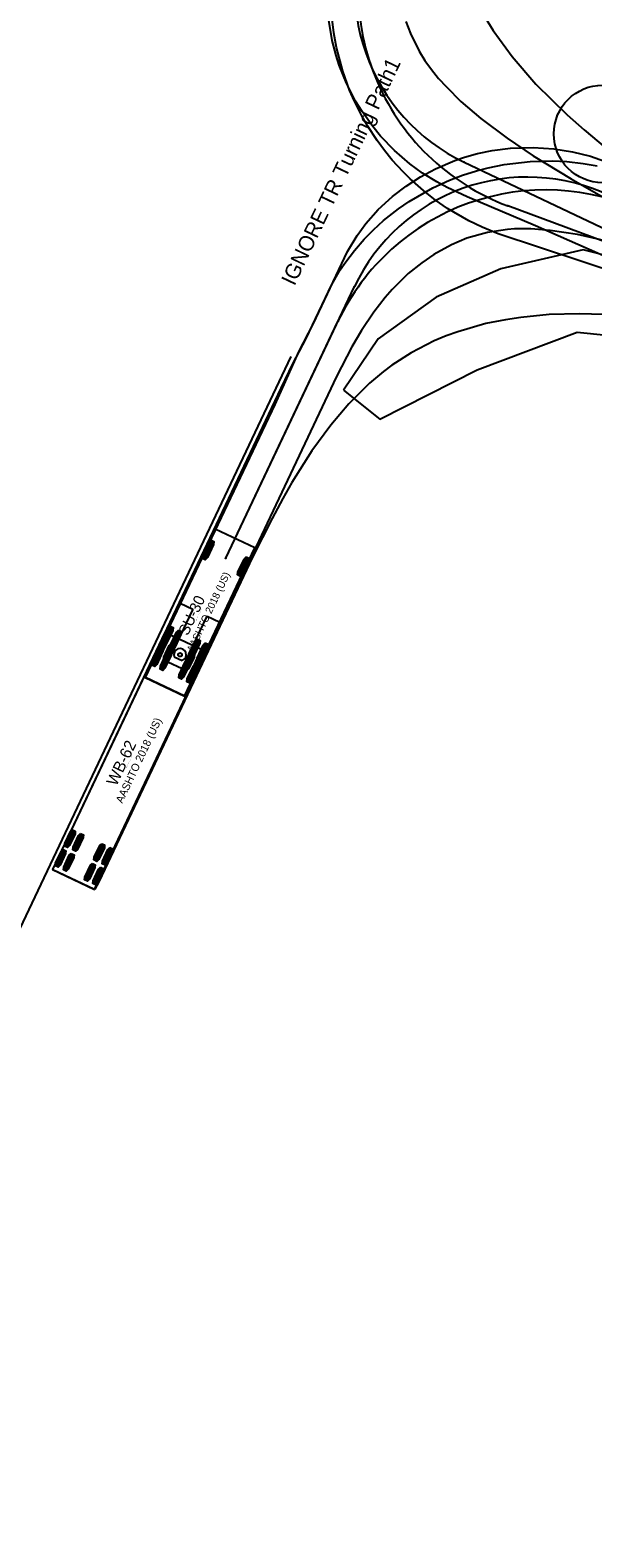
# Model space of a CAD drawing. Extents: x 186128 to 186702, y 352195 to 353183.
# Drawn here: x 186398.8 to 186501.6, y 352684.3 to 352960 of the extents above; entities that cross this region are included whole.
import ezdxf

# ---------------------------------------------------------------- set-up
doc = ezdxf.new("R2010")
doc.units = 0
for name, color, linetype in [('GK_Drainage_Nodes', 7, 'Continuous'), ('SV_X_Control_Cells_Found', 7, 'Continuous'), ('SV_X_Shot_Marker', 7, 'Continuous')]:
    doc.layers.add(name, color=color, linetype=linetype)

msp = doc.modelspace()

# ---------------------------------------------------------------- linework, layer by layer
at = {"layer": 'GK_Drainage_Nodes'}
msp.add_lwpolyline([(186455.99, 352894.17), (186462.66, 352888.85), (186480.45, 352897.88), (186498.71, 352904.75), (186519.8, 352902.65), (186541.45, 352895.17), (186544.58, 352902.76), (186518.65, 352915.08), (186499.81, 352919.82), (186484.74, 352916.37), (186472.96, 352911.19), (186462.32, 352903.52)], close=True, dxfattribs=at)
msp.add_circle((186503.37, 352941), 8.93, dxfattribs=at)
at = {"layer": 'SV_X_Control_Cells_Found'}
for p, q in [((186478.03, 352935.86), (186665.94, 352846.44)), ((186434.48, 352863.41), (186458, 352913.08)), ((186344.15, 352684.3), (186446.42, 352900.31)), ((186432.58, 352868.73), (186419.74, 352841.62)), ((186431.77, 352866.54), (186430.34, 352863.52)), ((186439.81, 352865.31), (186432.58, 352868.73)), ((186432.58, 352868.73), (186432.58, 352868.73)), ((186426.97, 352838.2), (186439.81, 352865.31)), ((186431.96, 352866.45), (186430.53, 352863.43)), ((186432.15, 352866.36), (186430.72, 352863.34)), ((186438.25, 352863.47), (186436.82, 352860.46)), ((186438.44, 352863.38), (186437.01, 352860.37)), ((186438.62, 352863.29), (186437.2, 352860.28)), ((186423.21, 352848.46), (186421.78, 352845.45)), ((186423.4, 352848.37), (186421.97, 352845.36)), ((186423.59, 352848.28), (186422.16, 352845.27)), ((186424.57, 352847.82), (186423.14, 352844.8)), ((186424.76, 352847.73), (186423.33, 352844.72)), ((186424.94, 352847.64), (186423.52, 352844.63)), ((186428.33, 352846.03), (186426.91, 352843.02)), ((186428.52, 352845.95), (186427.09, 352842.93)), ((186428.71, 352845.86), (186427.28, 352842.84)), ((186429.69, 352845.39), (186428.26, 352842.38)), ((186429.88, 352845.3), (186428.45, 352842.29)), ((186430.07, 352845.21), (186428.64, 352842.2)), ((186419.74, 352841.62), (186426.97, 352838.2))]:
    msp.add_line(p, q, dxfattribs=at)
for points in [[(186505.05, 352918.05), (186491.07, 352924.21), (186478.6, 352929.53), (186474.96, 352931.2), (186473.06, 352932.22), (186470.44, 352933.86), (186468.11, 352935.57), (186465.35, 352937.96), (186462.79, 352940.62), (186461.35, 352942.36), (186459.41, 352945.08), (186458.23, 352947.02), (186456.56, 352950.26), (186455.21, 352953.61), (186454.65, 352955.32), (186453.93, 352958.07), (186453.31, 352961.78)], [(186467.42, 352961.58), (186468.24, 352959.38), (186469.81, 352956.17), (186470.89, 352954.43), (186472.08, 352952.79), (186473.39, 352951.15), (186474.8, 352949.61), (186477.46, 352946.95), (186481.13, 352943.8), (186485.89, 352940.22), (186490.68, 352937.01), (186497.6, 352932.78), (186503.05, 352929.69), (186509.05, 352926.44), (186518.63, 352921.46), (186534.9, 352913.39), (186572.4, 352895.37), (186616.63, 352874.31)], [(186504.13, 352921.4), (186498.78, 352922.61), (186493.76, 352923.37), (186490.21, 352923.63), (186487.23, 352923.63), (186485.95, 352923.53), (186482.34, 352923.01), (186478.57, 352921.92), (186475.75, 352920.74), (186472.53, 352918.97), (186470.3, 352917.46), (186467.84, 352915.46), (186464.89, 352912.57), (186463.61, 352911.1), (186461.54, 352908.44), (186459.28, 352905.06), (186457.54, 352902.07), (186454.75, 352896.66), (186427.85, 352839.8), (186427.09, 352838.26), (186426.99, 352838.23), (186419.81, 352841.64), (186443.5, 352891.51), (186447.86, 352901.16), (186450.45, 352906.21), (186456.75, 352919.53), (186458.49, 352922.45), (186460.1, 352924.61), (186462.36, 352927.17), (186464.95, 352929.57), (186467.45, 352931.47), (186470.07, 352933.18), (186472.79, 352934.62), (186476.34, 352936.13), (186478.14, 352936.75), (186480.5, 352937.41), (186483.19, 352937.97), (186486.54, 352938.39), (186490.67, 352938.52), (186494.45, 352938.26), (186497.83, 352937.74), (186501.14, 352936.92), (186504.58, 352935.74)], [(186431.72, 352866.56), (186432.19, 352866.34), (186432.13, 352865.85), (186431.11, 352863.68), (186430.77, 352863.32), (186430.3, 352863.55), (186430.35, 352864.03), (186431.38, 352866.2), (186431.72, 352866.56)], [(186438.2, 352863.49), (186438.67, 352863.27), (186438.61, 352862.78), (186437.59, 352860.61), (186437.24, 352860.26), (186436.77, 352860.48), (186436.83, 352860.97), (186437.86, 352863.14), (186438.2, 352863.49)], [(186423.16, 352848.48), (186423.63, 352848.26), (186423.58, 352847.77), (186422.55, 352845.6), (186422.21, 352845.25), (186421.74, 352845.47), (186421.8, 352845.96), (186422.82, 352848.13), (186423.16, 352848.48)], [(186424.52, 352847.84), (186424.99, 352847.62), (186424.93, 352847.13), (186423.91, 352844.96), (186423.56, 352844.6), (186423.09, 352844.83), (186423.15, 352845.32), (186424.18, 352847.48), (186424.52, 352847.84)], [(186428.29, 352846.06), (186428.76, 352845.83), (186428.7, 352845.35), (186427.67, 352843.18), (186427.33, 352842.82), (186426.86, 352843.04), (186426.92, 352843.53), (186427.94, 352845.7), (186428.29, 352846.06)], [(186429.64, 352845.41), (186430.11, 352845.19), (186430.05, 352844.7), (186429.03, 352842.53), (186428.69, 352842.18), (186428.22, 352842.4), (186428.27, 352842.89), (186429.3, 352845.06), (186429.64, 352845.41)]]:
    msp.add_lwpolyline(points, dxfattribs=at)
for centre in [(186478.03, 352935.86), (186478.03, 352935.86), (186458, 352913.08), (186458, 352913.08), (186434.48, 352863.41)]:
    msp.add_circle(centre, 0.0417, dxfattribs=at)
for centre, start, end in [((186493.07, 352967.47), 154.3603, 244.5505), ((186489.64, 352898.11), 64.5505, 154.6637)]:
    msp.add_arc(centre, 35, start, end, dxfattribs=at)
at = {"layer": 'SV_X_Shot_Marker'}
for p, q in [((186526.61, 352912.75), (186486.06, 352927.85)), ((186434.48, 352863.41), (186455, 352906.74)), ((186432.58, 352868.73), (186426.16, 352855.18)), ((186431.86, 352866.68), (186430.29, 352863.36)), ((186432.07, 352866.58), (186430.5, 352863.27)), ((186439.81, 352865.31), (186432.58, 352868.73)), ((186432.58, 352868.73), (186432.58, 352868.73)), ((186432.27, 352866.48), (186430.71, 352863.17)), ((186433.39, 352851.75), (186439.81, 352865.31)), ((186438.26, 352863.65), (186436.69, 352860.33)), ((186438.47, 352863.55), (186436.9, 352860.23)), ((186438.68, 352863.45), (186437.11, 352860.14)), ((186428.48, 352854.08), (186423.94, 352844.5)), ((186426.16, 352855.18), (186428.48, 352854.08)), ((186426.54, 352843.27), (186431.07, 352852.85)), ((186431.07, 352852.85), (186433.39, 352851.75)), ((186424.41, 352850.95), (186422.84, 352847.64)), ((186424.62, 352850.85), (186423.05, 352847.54)), ((186424.83, 352850.75), (186423.26, 352847.44)), ((186425.91, 352850.24), (186424.34, 352846.93)), ((186426.11, 352850.15), (186424.54, 352846.83)), ((186426.32, 352850.05), (186424.75, 352846.73)), ((186423.37, 352849.86), (186402.83, 352806.48)), ((186431.05, 352846.22), (186423.37, 352849.86)), ((186423.37, 352849.86), (186423.37, 352849.86)), ((186429.32, 352848.63), (186427.76, 352845.31)), ((186429.53, 352848.53), (186427.96, 352845.21)), ((186429.74, 352848.43), (186428.17, 352845.12)), ((186430.82, 352847.92), (186429.25, 352844.61)), ((186431.02, 352847.82), (186429.45, 352844.51)), ((186431.23, 352847.72), (186429.66, 352844.41)), ((186410.51, 352802.84), (186431.05, 352846.22)), ((186422.62, 352847.15), (186421.05, 352843.84)), ((186422.82, 352847.06), (186421.25, 352843.74)), ((186423.03, 352846.96), (186421.46, 352843.64)), ((186424.11, 352846.45), (186422.54, 352843.13)), ((186424.32, 352846.35), (186422.75, 352843.04)), ((186424.52, 352846.25), (186422.95, 352842.94)), ((186423.94, 352844.5), (186426.54, 352843.27)), ((186425.06, 352845.4), (186426.52, 352844.71)), ((186427.53, 352844.83), (186425.96, 352841.52)), ((186427.73, 352844.73), (186426.17, 352841.42)), ((186427.94, 352844.63), (186426.37, 352841.32)), ((186429.02, 352844.12), (186427.45, 352840.81)), ((186429.23, 352844.03), (186427.66, 352840.71)), ((186429.43, 352843.93), (186427.86, 352840.61)), ((186406.52, 352813.75), (186405.11, 352810.76)), ((186406.73, 352813.65), (186405.32, 352810.66)), ((186406.94, 352813.55), (186405.52, 352810.57)), ((186408.01, 352813.04), (186406.6, 352810.06)), ((186408.22, 352812.94), (186406.81, 352809.96)), ((186408.43, 352812.84), (186407.01, 352809.86)), ((186404.81, 352810.13), (186403.4, 352807.15)), ((186405.02, 352810.03), (186403.6, 352807.05)), ((186405.22, 352809.93), (186403.81, 352806.95)), ((186406.3, 352809.42), (186404.89, 352806.44)), ((186406.51, 352809.33), (186405.1, 352806.34)), ((186406.72, 352809.23), (186405.3, 352806.25)), ((186411.88, 352811.21), (186410.47, 352808.22)), ((186412.09, 352811.11), (186410.68, 352808.13)), ((186412.3, 352811.01), (186410.89, 352808.03)), ((186413.38, 352810.5), (186411.96, 352807.52)), ((186413.58, 352810.4), (186412.17, 352807.42)), ((186413.79, 352810.3), (186412.38, 352807.32)), ((186402.83, 352806.48), (186410.51, 352802.84)), ((186410.17, 352807.59), (186408.76, 352804.61)), ((186410.38, 352807.49), (186408.97, 352804.51)), ((186410.59, 352807.4), (186409.17, 352804.41)), ((186411.66, 352806.89), (186410.25, 352803.9)), ((186411.87, 352806.79), (186410.46, 352803.8)), ((186412.08, 352806.69), (186410.67, 352803.71))]:
    msp.add_line(p, q, dxfattribs=at)
for points in [[(186481.11, 352963.55), (186483.34, 352959.94), (186486.82, 352955.15), (186491.18, 352950.13), (186496.89, 352944.49), (186499.97, 352941.73), (186503.81, 352938.55), (186510.34, 352933.53), (186519.89, 352926.87), (186527.3, 352922.08), (186538.72, 352915.26), (186549.81, 352909.02), (186561.62, 352902.66), (186576.55, 352894.88), (186600.33, 352882.97), (186617.33, 352874.71)], [(186506.93, 352915.22), (186484.29, 352922.74), (186481.34, 352923.95), (186478.91, 352925.13), (186475.04, 352927.4), (186472.84, 352928.91), (186470.61, 352930.64), (186468.18, 352932.81), (186466.9, 352934.09), (186464.93, 352936.22), (186463.52, 352937.96), (186462.14, 352939.83), (186460.4, 352942.49), (186459.29, 352944.42), (186458.01, 352946.98), (186457.12, 352949.02), (186455.88, 352952.46), (186454.73, 352956.82), (186454.24, 352959.52), (186453.88, 352962.47)], [(186503.52, 352907.96), (186499.12, 352908.09), (186493.57, 352907.96), (186488.42, 352907.47), (186485.64, 352907.04), (186482.03, 352906.32), (186476.88, 352904.84), (186474.74, 352904.09), (186472.58, 352903.17), (186468.38, 352901), (186464.87, 352898.74), (186463.29, 352897.56), (186460.77, 352895.43), (186456.99, 352891.65), (186453.68, 352887.75), (186450.23, 352883.06), (186446.59, 352877.25), (186444.95, 352874.36), (186442.95, 352870.66), (186439.38, 352863.6), (186411.29, 352804.28), (186410.6, 352802.91), (186410.5, 352802.87), (186402.89, 352806.45), (186402.96, 352806.65), (186444.59, 352894.54), (186446.82, 352899.1), (186449.15, 352903.5), (186453.88, 352913.5), (186455.42, 352916.13), (186456.44, 352917.64), (186458.01, 352919.7), (186459.78, 352921.74), (186461.49, 352923.48), (186463.33, 352925.15), (186466.05, 352927.32), (186468.02, 352928.66), (186472.35, 352931.15), (186475.37, 352932.53), (186477.76, 352933.45), (186480.32, 352934.27), (186482.45, 352934.83), (186485.34, 352935.42), (186490.13, 352935.98), (186494.2, 352936.08), (186496.79, 352935.94), (186499.78, 352935.62), (186502.33, 352935.19)], [(186431.81, 352866.7), (186432.33, 352866.46), (186432.26, 352865.92), (186431.13, 352863.53), (186430.76, 352863.14), (186430.24, 352863.39), (186430.3, 352863.93), (186431.43, 352866.31), (186431.81, 352866.7)], [(186438.21, 352863.67), (186438.73, 352863.43), (186438.66, 352862.89), (186437.53, 352860.5), (186437.16, 352860.11), (186436.64, 352860.36), (186436.71, 352860.89), (186437.84, 352863.28), (186438.21, 352863.67)], [(186424.36, 352850.98), (186424.88, 352850.73), (186424.82, 352850.19), (186423.69, 352847.81), (186423.31, 352847.42), (186422.79, 352847.66), (186422.86, 352848.2), (186423.99, 352850.59), (186424.36, 352850.98)], [(186425.85, 352850.27), (186426.37, 352850.02), (186426.31, 352849.49), (186425.18, 352847.1), (186424.8, 352846.71), (186424.28, 352846.96), (186424.35, 352847.49), (186425.48, 352849.88), (186425.85, 352850.27)], [(186429.27, 352848.65), (186429.79, 352848.41), (186429.73, 352847.87), (186428.6, 352845.48), (186428.22, 352845.09), (186427.7, 352845.34), (186427.77, 352845.87), (186428.9, 352848.26), (186429.27, 352848.65)], [(186430.76, 352847.94), (186431.28, 352847.7), (186431.22, 352847.16), (186430.09, 352844.78), (186429.71, 352844.39), (186429.2, 352844.63), (186429.26, 352845.17), (186430.39, 352847.55), (186430.76, 352847.94)], [(186422.57, 352847.18), (186423.08, 352846.93), (186423.02, 352846.4), (186421.89, 352844.01), (186421.51, 352843.62), (186421, 352843.87), (186421.06, 352844.4), (186422.19, 352846.79), (186422.57, 352847.18)], [(186424.06, 352846.47), (186424.57, 352846.23), (186424.51, 352845.69), (186423.38, 352843.3), (186423, 352842.91), (186422.49, 352843.16), (186422.55, 352843.7), (186423.68, 352846.08), (186424.06, 352846.47)], [(186427.48, 352844.85), (186427.99, 352844.61), (186427.93, 352844.07), (186426.8, 352841.69), (186426.42, 352841.3), (186425.91, 352841.54), (186425.97, 352842.08), (186427.1, 352844.46), (186427.48, 352844.85)], [(186428.97, 352844.15), (186429.48, 352843.9), (186429.42, 352843.37), (186428.29, 352840.98), (186427.92, 352840.59), (186427.4, 352840.83), (186427.46, 352841.37), (186428.59, 352843.76), (186428.97, 352844.15)], [(186406.47, 352813.77), (186406.99, 352813.53), (186406.95, 352813.03), (186405.93, 352810.89), (186405.58, 352810.54), (186405.06, 352810.79), (186405.1, 352811.28), (186406.12, 352813.43), (186406.47, 352813.77)], [(186407.96, 352813.06), (186408.48, 352812.82), (186408.44, 352812.33), (186407.42, 352810.18), (186407.07, 352809.84), (186406.55, 352810.08), (186406.59, 352810.57), (186407.61, 352812.72), (186407.96, 352813.06)], [(186404.76, 352810.15), (186405.28, 352809.91), (186405.23, 352809.42), (186404.22, 352807.27), (186403.86, 352806.93), (186403.35, 352807.17), (186403.39, 352807.66), (186404.41, 352809.81), (186404.76, 352810.15)], [(186406.25, 352809.45), (186406.77, 352809.2), (186406.72, 352808.71), (186405.71, 352806.57), (186405.35, 352806.22), (186404.84, 352806.47), (186404.88, 352806.96), (186405.9, 352809.1), (186406.25, 352809.45)], [(186411.83, 352811.23), (186412.35, 352810.99), (186412.31, 352810.49), (186411.29, 352808.35), (186410.94, 352808), (186410.42, 352808.25), (186410.46, 352808.74), (186411.48, 352810.89), (186411.83, 352811.23)], [(186413.32, 352810.52), (186413.84, 352810.28), (186413.8, 352809.79), (186412.78, 352807.64), (186412.43, 352807.3), (186411.91, 352807.54), (186411.95, 352808.03), (186412.97, 352810.18), (186413.32, 352810.52)], [(186410.12, 352807.62), (186410.64, 352807.37), (186410.6, 352806.88), (186409.58, 352804.73), (186409.23, 352804.39), (186408.71, 352804.63), (186408.75, 352805.12), (186409.77, 352807.27), (186410.12, 352807.62)], [(186411.61, 352806.91), (186412.13, 352806.66), (186412.09, 352806.17), (186411.07, 352804.03), (186410.72, 352803.68), (186410.2, 352803.93), (186410.24, 352804.42), (186411.26, 352806.57), (186411.61, 352806.91)]]:
    msp.add_lwpolyline(points, dxfattribs=at)
for centre, radius in [((186486.06, 352927.85), 0.0417), ((186486.06, 352927.85), 0.0417), ((186455, 352906.74), 0.0417), ((186455, 352906.74), 0.0417), ((186434.48, 352863.41), 0.0417), ((186426.14, 352845.78), 0.34)]:
    msp.add_circle(centre, radius, dxfattribs=at)
for centre, radius, start, end in [((186500.72, 352967.21), 42, 154.3603, 249.5711), ((186492.96, 352888.77), 42, 64.5505, 154.6637), ((186426.14, 352845.78), 1.14, 289.6637, 199.6637)]:
    msp.add_arc(centre, radius, start, end, dxfattribs=at)

# ---------------------------------------------------------------- texts
at = {"layer": 'SV_X_Control_Cells_Found'}
for s, height, rotation, p in [('IGNORE TR Turning Path1', 2.8, 64.5098, (186447.03, 352913.09)), ('AASHTO 2018 (US)', 1.3333, 64.6637, (186428.5, 352846.09)), ('SU-30', 2, 64.6637, (186427.55, 352849.14)), ('(c) 2025 Transoft Solutions, Inc. All rights reserved.', 0.08, 64.6637, (186429.11, 352851.97))]:
    msp.add_text(s, height=height, rotation=rotation, dxfattribs=at).set_placement(p)
at = {"layer": 'SV_X_Shot_Marker'}
for s, height, p in [('AASHTO 2018 (US)', 1.4167, (186415.59, 352818.51)), ('WB-62', 2.125, (186414.51, 352821.62)), ('(c) 2025 Transoft Solutions, Inc. All rights reserved.', 0.085, (186416.23, 352824.76))]:
    msp.add_text(s, height=height, rotation=64.6637, dxfattribs=at).set_placement(p)

doc.saveas('drawing.dxf')
